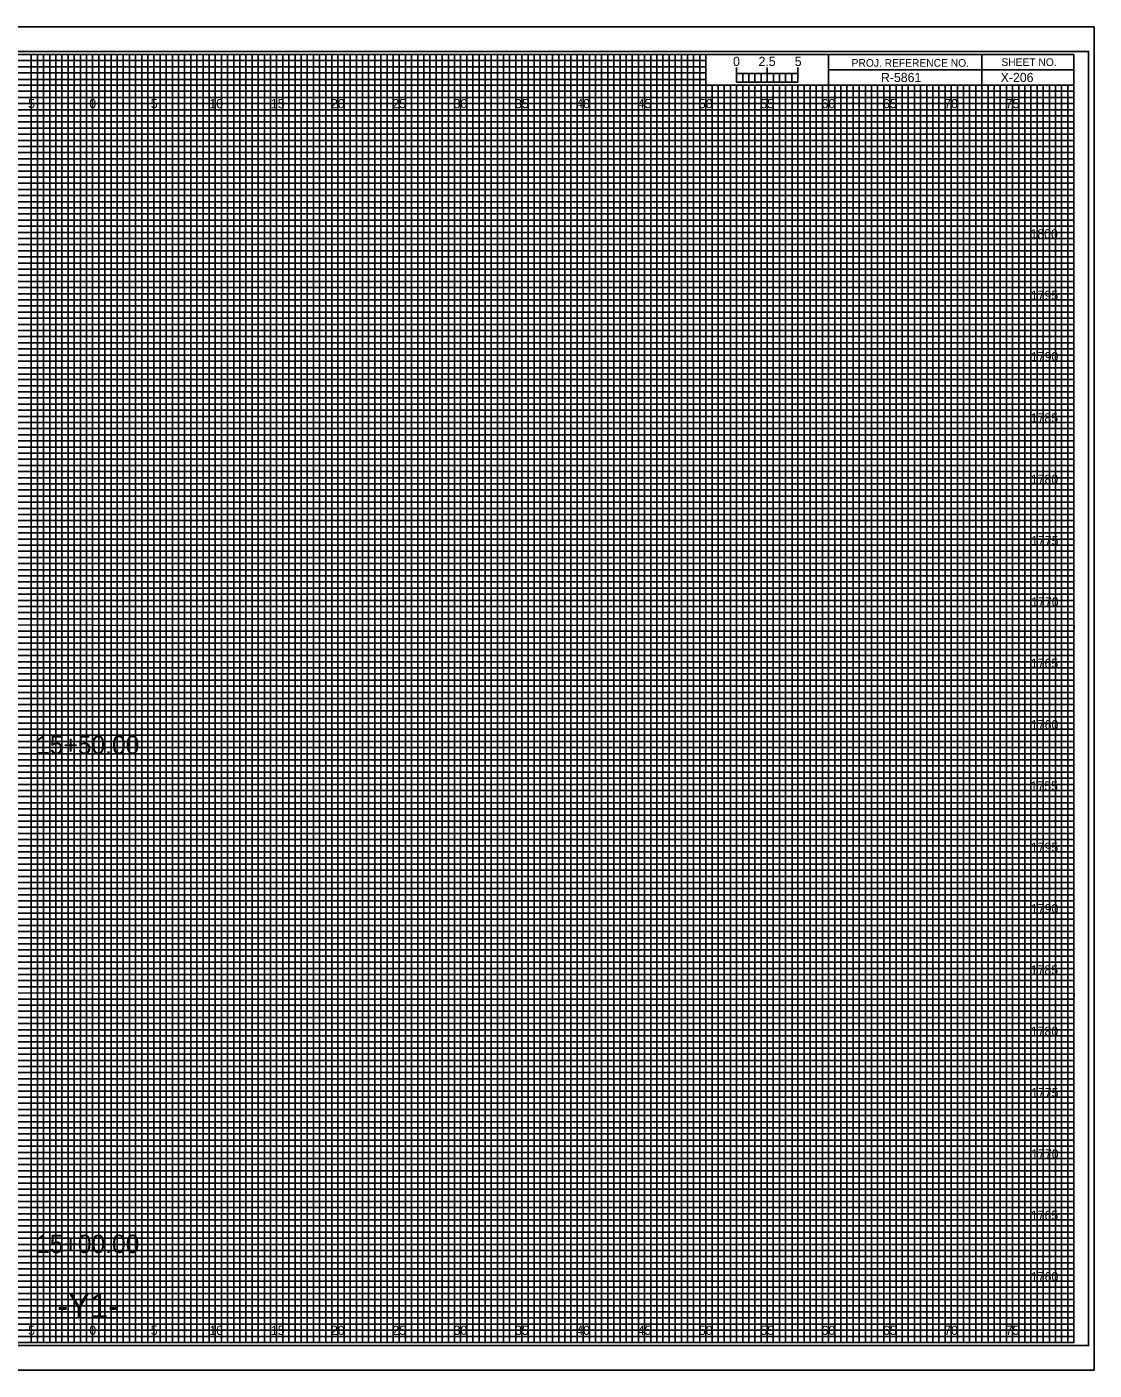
# Model space of a CAD drawing. Extents: x -7 to 162, y -2 to 767.
# Drawn here: x 74.6 to 161.7, y 547.8 to 657.2 of the extents above; entities that cross this region are included whole.
import ezdxf

# ---------------------------------------------------------------- set-up
doc = ezdxf.new("R2010")
doc.units = 0
for name, color, linetype in [('Prop Grid Mask', 7, 'Continuous'), ('Prop XS Alignment Label', 7, 'Continuous'), ('Prop XS Bar Scale Labels', 7, 'Continuous'), ('Prop XS Elevation Labels', 7, 'Continuous'), ('Prop XS Project Number', 7, 'Continuous'), ('Prop XS Sheet Number', 7, 'Continuous'), ('Prop XS Station Labels', 7, 'Continuous'), ('Sheet Cross Section CELL', 7, 'Continuous'), ('Sheet Cross Section Grid Major CELL', 7, 'Continuous'), ('Sheet Cross Section Grid Middle CELL', 7, 'Continuous'), ('Sheet Cross Section Grid Minor 1 CELL', 7, 'Continuous'), ('Sheet Cross Section Grid Minor 2 CELL', 7, 'Continuous'), ('Sheet Cross Section Scale CELL', 7, 'Continuous'), ('Sheet Cutting Line CELL', 7, 'Continuous'), ('Sheet DOT Grid CELL', 7, 'Continuous'), ('Sheet Plot Border Inside CELL', 7, 'Continuous'), ('Sheet Plot Border Outside CELL', 7, 'Continuous')]:
    doc.layers.add(name, color=color, linetype=linetype)

msp = doc.modelspace()

# ---------------------------------------------------------------- linework, layer by layer
at = {"layer": 'Sheet Cross Section CELL'}
for p, q in [((152.5, 655), (152.5, 652.5)), ((152.5, 652.5), (152.5, 655)), ((160, 653.75), (140, 653.75)), ((140, 653.75), (140, 652.5)), ((140, 652.5), (160, 652.5))]:
    msp.add_line(p, q, dxfattribs=at)
for points in [[(160, 655), (0, 655), (0, 550), (160, 550)], [(140, 655), (130, 655), (130, 652.51), (140, 652.51)], [(160, 655), (140, 655), (140, 652.5), (160, 652.5)]]:
    msp.add_lwpolyline(points, close=True, dxfattribs=at)
at = {"layer": 'Sheet Cross Section Grid Major CELL'}
for p, q in [((75, 655), (70, 655)), ((75, 550), (75, 655)), ((85, 655), (80, 655)), ((80, 655), (80, 550)), ((85, 550), (85, 655)), ((95, 655), (90, 655)), ((90, 655), (90, 550)), ((95, 550), (95, 655)), ((105, 655), (100, 655)), ((100, 655), (100, 550)), ((105, 550), (105, 655)), ((115, 655), (110, 655)), ((110, 655), (110, 550)), ((115, 550), (115, 655)), ((125, 655), (120, 655)), ((120, 655), (120, 550)), ((125, 550), (125, 655)), ((130, 655), (130, 550)), ((135, 550), (135, 652.5)), ((145, 652.5), (140, 652.5)), ((140, 652.5), (140, 550)), ((145, 550), (145, 652.5)), ((155, 652.5), (150, 652.5)), ((150, 652.5), (150, 550)), ((155, 550), (155, 652.5)), ((80, 550), (75, 550)), ((90, 550), (85, 550)), ((100, 550), (95, 550)), ((110, 550), (105, 550)), ((120, 550), (115, 550)), ((130, 550), (125, 550)), ((140, 550), (135, 550)), ((150, 550), (145, 550)), ((160, 550), (155, 550)), ((160, 550), (160, 550))]:
    msp.add_line(p, q, dxfattribs=at)
for points in [[(0, 650), (160, 650), (160, 645), (0, 645)], [(0, 640), (160, 640), (160, 635), (0, 635)], [(0, 630), (160, 630), (160, 625), (0, 625)], [(0, 620), (160, 620), (160, 615), (0, 615)], [(0, 610), (160, 610), (160, 605), (0, 605)], [(0, 600), (160, 600), (160, 595), (0, 595)], [(0, 590), (160, 590), (160, 585), (0, 585)], [(0, 580), (160, 580), (160, 575), (0, 575)], [(0, 570), (160, 570), (160, 565), (0, 565)], [(0, 560), (160, 560), (160, 555), (0, 555)]]:
    msp.add_lwpolyline(points, dxfattribs=at)
at = {"layer": 'Sheet Cross Section Grid Middle CELL'}
for points in [[(72.5, 550), (77.5, 550), (77.5, 655), (82.5, 655), (82.5, 550), (87.5, 550), (87.5, 655), (92.5, 655), (92.5, 550), (97.5, 550), (97.5, 655), (102.5, 655), (102.5, 550), (107.5, 550), (107.5, 655), (112.5, 655), (112.5, 550), (117.5, 550), (117.5, 655), (122.5, 655), (122.5, 550), (127.5, 550), (127.5, 655), (129.97, 655), (130, 655), (130, 652.5), (132.5, 652.5), (132.5, 550), (137.5, 550), (137.5, 652.5), (142.5, 652.5), (142.5, 550), (147.5, 550), (147.5, 652.5), (152.5, 652.5), (152.5, 550), (157.5, 550), (157.5, 652.5)], [(0, 652.5), (137.5, 652.5)], [(0, 642.5), (160, 642.5), (160, 647.5), (0, 647.5)], [(0, 632.5), (160, 632.5), (160, 637.5), (0, 637.5)], [(0, 622.5), (160, 622.5), (160, 627.5), (0, 627.5)], [(0, 612.5), (160, 612.5), (160, 617.5), (0, 617.5)], [(0, 602.5), (160, 602.5), (160, 607.5), (0, 607.5)], [(0, 592.5), (160, 592.5), (160, 597.5), (0, 597.5)], [(0, 582.5), (160, 582.5), (160, 587.5), (0, 587.5)], [(0, 572.5), (160, 572.5), (160, 577.5), (0, 577.5)], [(0, 562.5), (160, 562.5), (160, 567.5), (0, 567.5)], [(0, 552.5), (160, 552.5), (160, 557.5), (0, 557.5)]]:
    msp.add_lwpolyline(points, dxfattribs=at)
at = {"layer": 'Sheet Cross Section Grid Minor 1 CELL'}
for p, q in [((0, 654.5), (130, 654.5)), ((130, 653.99), (0, 653.99)), ((130, 654.5), (130, 653.99)), ((0, 653.5), (130, 653.5)), ((130, 652.95), (0, 652.95)), ((130, 653.5), (130, 652.95)), ((0, 652), (160, 652))]:
    msp.add_line(p, q, dxfattribs=at)
for points in [[(0, 651.5), (135, 651.5), (160, 651.5), (160, 651), (0, 651)], [(0, 650.5), (160, 650.5), (160, 649.5), (0, 649.5)], [(0, 649), (160, 649), (160, 648.5), (0, 648.49)], [(0, 648), (160, 648), (160, 647), (0, 647)], [(0, 646.5), (160, 646.5), (160, 646), (0, 646)], [(0, 645.5), (160, 645.5), (160, 644.5), (0, 644.5)], [(0, 644), (160, 644), (160, 643.5), (0, 643.5)], [(0, 643), (160, 643), (160, 642), (0, 642)], [(0, 641.5), (160, 641.5), (160, 641), (0, 641)], [(0, 640.5), (160, 640.5), (160, 639.5), (0, 639.5)], [(0, 639), (160, 639), (160, 638.5), (0, 638.5)], [(0, 638), (160, 638), (160, 636.98), (160, 636.5), (160, 636), (0, 636)], [(0, 637), (160, 637), (160, 636.5), (0, 636.5)], [(0, 635.5), (160, 635.5), (160, 634.5), (0, 634.51)], [(0, 634.51), (160, 634.5), (160, 634), (0, 634)], [(0, 633.5), (160, 633.5), (160, 633), (0, 633)], [(0, 632), (160, 632), (160, 631.5), (0, 631.5)], [(0, 631), (160, 631), (160, 630.5), (0, 630.5)], [(-0.04, 629.45), (160, 629.45), (160, 628.94), (-0.04, 628.94)], [(0, 628.5), (160, 628.5), (160, 628), (0, 628)], [(0, 627), (160, 627), (160, 626.5), (0, 626.5)], [(0, 626), (160, 626), (160, 625.5), (0, 625.5)], [(0, 624.5), (160, 624.5), (160, 624), (0, 624)], [(0, 623.5), (160, 623.5), (160, 623), (0, 623)], [(0, 622), (160, 622), (160, 621.5), (0, 621.5)], [(0, 621), (160, 621), (160, 620.5), (0, 620.5)], [(0, 619.5), (160, 619.5), (160, 618.99), (0, 619)], [(0, 618.5), (160, 618.5), (160, 618), (0, 618)], [(0, 617), (160, 617), (160, 616.5), (0, 616.5)], [(0, 616), (160, 616), (160, 615.5), (0, 615.5)], [(0, 614.5), (160, 614.5), (160, 614), (0, 614)], [(0, 613.5), (160, 613.5), (160, 613), (0, 613)], [(0, 612), (160, 612), (160, 611.5), (0, 611.5)], [(0, 611), (160, 611), (160, 610.5), (0, 610.5)], [(0, 609.5), (160, 609.5), (160, 609), (0, 609)], [(0, 608.5), (160.03, 608.46), (160, 608), (0, 608)], [(0, 607), (160, 607), (160, 606.5), (0, 606.5)], [(0, 606), (160, 606), (160, 605.5), (0, 605.5)], [(0, 604.5), (160, 604.5), (160, 604), (0, 604)], [(0, 603.5), (160, 603.5), (160, 603), (0, 603)], [(0, 602), (160, 602), (160, 601.5), (0, 601.5)], [(0, 601), (160, 601), (160, 600.5), (0, 600.5)], [(0, 599.5), (160, 599.5), (160, 599), (0, 599)], [(0, 598.5), (160, 598.5), (160, 598), (0, 598)], [(0, 597), (160, 597), (160, 596.5), (0, 596.5)], [(0, 596), (160, 596), (160, 595.5), (0, 595.5)], [(0, 594.5), (160, 594.5), (160, 594), (0, 594)], [(0, 593.5), (160, 593.5), (160, 593), (0, 593)], [(0, 592), (160, 592), (160, 591.5), (0, 591.5)], [(0, 591), (160, 591), (160, 590.5), (0, 590.5)], [(0, 589.5), (160, 589.5), (160, 588.99), (0, 589)], [(0, 588.5), (160, 588.5), (160, 588), (0, 588)], [(0, 587), (160, 587), (160, 586.5), (0, 586.5)], [(0, 586), (160, 586), (160, 585.5), (0, 585.5)], [(0, 584.5), (160, 584.5), (160, 584), (0, 584)], [(0, 583.5), (160, 583.5), (160, 583), (0, 583)], [(0, 582), (160, 582), (160, 581.5), (0, 581.5)], [(0, 581), (160, 581), (160, 580.5), (0, 580.5)], [(0, 579.5), (160, 579.5), (160, 579), (0, 579)], [(0, 578.5), (160.03, 578.46), (160, 578), (0, 578)], [(0, 577), (160, 577), (160, 576.5), (0, 576.5)], [(0, 576), (160, 576), (160, 575.5), (0, 575.5)], [(0, 574.5), (160, 574.5), (160, 574), (0, 574)], [(0, 573.5), (160, 573.5), (160, 573), (0, 573)], [(0, 572), (160, 572), (160, 571.5), (0, 571.5)], [(0, 571), (160, 571), (160, 570.5), (0, 570.5)], [(0, 569.5), (160, 569.5), (160, 569), (0, 569)], [(0, 568.5), (160, 568.5), (160, 568), (0, 568)], [(0, 567), (160, 567), (160, 566.5), (0, 566.5)], [(0, 566), (160, 566), (160, 565.5), (0, 565.5)], [(0, 564.5), (160, 564.5), (160, 564), (0, 564)], [(0, 563.5), (160, 563.5), (160, 563), (0, 563)], [(0, 562), (160, 562), (160, 561.5), (0, 561.5)], [(0, 561), (160, 561), (160, 560.5), (0, 560.5)], [(0, 559.5), (160, 559.5), (160, 559), (0, 559)], [(0, 558.5), (160, 558.5), (160, 558), (0, 558)], [(0, 557), (160, 557), (160, 556.5), (0, 556.5)], [(0, 556), (160, 556), (160, 555.5), (0, 555.5)], [(0, 554.5), (160, 554.5), (160, 554), (0, 554)], [(0, 553.5), (160, 553.5), (160, 553), (0, 553)], [(0, 552), (160, 552), (160, 551.5), (0, 551.5)], [(0, 551), (160, 551), (160, 550.5), (0, 550.5)]]:
    msp.add_lwpolyline(points, dxfattribs=at)
at = {"layer": 'Sheet Cross Section Grid Minor 2 CELL'}
for p, q in [((133.5, 652.5), (133, 652.5)), ((133, 652.5), (133, 550)), ((133.5, 550), (133.5, 652.5)), ((134.5, 652.5), (134, 652.5)), ((134, 652.5), (134, 550)), ((134.5, 550), (134.5, 652.5)), ((133, 550), (132.5, 550)), ((134, 550), (133.5, 550))]:
    msp.add_line(p, q, dxfattribs=at)
for points in [[(75, 550), (75.5, 550), (75.5, 655), (76, 655), (76, 550)], [(76, 550), (76.5, 550), (76.5, 655), (77, 655), (77, 550)], [(77.5, 550), (78, 550), (78, 655), (78.5, 655), (78.5, 550)], [(78.5, 550), (79, 550), (79, 655), (79.5, 655), (79.5, 550)], [(80, 550), (80.5, 550), (80.5, 655), (81, 655), (81, 550)], [(81, 550), (81.5, 550), (81.5, 655), (82, 655), (82, 550)], [(82.5, 550), (83, 550), (83, 655), (83.5, 655), (83.5, 550)], [(83.5, 550), (84, 550), (84, 655), (84.5, 655), (84.5, 550)], [(85, 550), (85.5, 550), (85.5, 655), (86, 655), (86, 550)], [(86, 550), (86.5, 550), (86.5, 655), (87, 655), (87, 550)], [(87.5, 550), (88, 550), (88, 655), (88.5, 655), (88.5, 550)], [(88.5, 550), (89, 550), (89, 655), (89.5, 655), (89.5, 550)], [(90, 550), (90.5, 550), (90.5, 655), (91, 655), (91, 550)], [(91, 550), (91.5, 550), (91.5, 655), (92, 655), (92, 550)], [(92.5, 550), (93, 550), (93, 655), (93.5, 655), (93.5, 550)], [(93.5, 550), (94, 550), (94, 655), (94.5, 655), (94.5, 550)], [(95, 550), (95.5, 550), (95.5, 655), (96, 655), (96, 550)], [(96, 550), (96.5, 550), (96.5, 655), (97, 655), (97, 550)], [(97.5, 550), (98, 550), (98, 655), (98.5, 655), (98.5, 550)], [(98.5, 550), (99, 550), (99, 655), (99.5, 655), (99.5, 550)], [(100, 550), (100.5, 550), (100.5, 655), (101, 655), (101, 550)], [(101, 550), (101.5, 550), (101.5, 655), (102, 655), (102, 550)], [(102.5, 550), (103, 550), (103, 655), (103.5, 655), (103.5, 550)], [(103.5, 550), (104, 550), (104, 655), (104.5, 655), (104.5, 550)], [(105, 550), (105.5, 550), (105.5, 655), (106, 655), (106, 550)], [(106, 550), (106.5, 550), (106.5, 655), (107, 655), (107, 550)], [(107.5, 550), (108, 550), (108, 655), (108.5, 655), (108.5, 550)], [(108.5, 550), (109, 550), (109, 655), (109.5, 655), (109.5, 550)], [(110, 550), (110.5, 550), (110.5, 655), (111, 655), (111, 550)], [(111, 550), (111.5, 550), (111.5, 655), (112, 655), (112, 550)], [(112.5, 550), (113, 550), (113, 655), (113.5, 655), (113.5, 550)], [(113.5, 550), (114, 550), (114, 655), (114.5, 655), (114.5, 550)], [(115, 550), (115.5, 550), (115.5, 655), (116, 655), (116, 550)], [(116, 550), (116.5, 550), (116.5, 655), (117, 655), (117, 550)], [(117.5, 550), (118, 550), (118, 655), (118.5, 655), (118.5, 550)], [(118.5, 550), (119, 550), (119, 655), (119.5, 655), (119.5, 550)], [(120, 550), (120.5, 550), (120.5, 655), (121, 655), (121, 550)], [(121, 550), (121.5, 550), (121.5, 655), (122, 655), (122, 550)], [(122.5, 550), (123, 550), (123, 655), (123.5, 655), (123.5, 550)], [(123.5, 550), (124, 550), (124, 655), (124.5, 655), (124.5, 550)], [(125, 550), (125.5, 550), (125.5, 655), (126, 655), (126, 550)], [(126, 550), (126.5, 550), (126.5, 655), (127, 655), (127, 550)], [(127.5, 550), (128, 550), (128, 655), (128.5, 655), (128.5, 550)], [(128.5, 550), (129, 550), (129, 655), (129.5, 655), (129.5, 550)], [(130, 550), (130.5, 550), (130.5, 652.5), (131.01, 652.5), (131.01, 550)], [(131, 550), (131.5, 550), (131.5, 652.5), (132, 652.5), (132, 550)], [(135, 550), (135.49, 550), (135.49, 652.5), (136, 652.5), (136, 550)], [(136, 550), (136.5, 550), (136.5, 652.5), (137.03, 652.5), (137.03, 550)], [(137.5, 550), (138, 550), (138, 652.5), (138.5, 652.5), (138.5, 550)], [(138.5, 550), (139, 550), (139, 652.5), (139.5, 652.5), (139.5, 550)], [(140, 550), (140.5, 550), (140.5, 652.5), (141, 652.5), (141, 550)], [(141, 550), (141.5, 550), (141.5, 652.5), (142, 652.5), (142, 550)], [(142.5, 550), (143, 550), (143, 652.5), (143.5, 652.5), (143.5, 550)], [(143.5, 550), (144, 550), (144, 652.5), (144.5, 652.5), (144.5, 550)], [(145, 550), (145.5, 550), (145.5, 652.5), (146, 652.5), (146, 550)], [(146, 550), (146.5, 550), (146.5, 652.5), (147, 652.5), (147, 550)], [(147.5, 550), (148, 550), (148, 652.5), (148.5, 652.5), (148.5, 550)], [(148.5, 550), (149, 550), (149, 652.5), (149.5, 652.5), (149.5, 550)], [(150, 550), (150.5, 550), (150.5, 652.5), (151, 652.5), (151, 550)], [(151, 550), (151.5, 550), (151.5, 652.5), (152, 652.5), (152, 550)], [(152.5, 550), (153, 550), (153, 652.5), (153.5, 652.5), (153.5, 550)], [(153.5, 550), (154, 550), (154, 652.5), (154.5, 652.5), (154.5, 550)], [(155, 550), (155.5, 550), (155.5, 652.5), (156, 652.5), (156, 550)], [(156, 550), (156.5, 550), (156.5, 652.5), (157, 652.5), (157, 550)], [(157.5, 550), (158, 550), (158, 652.5), (158.5, 652.5), (158.5, 550)], [(158.5, 550), (159, 550), (159, 652.5), (159.5, 652.5), (159.5, 550)]]:
    msp.add_lwpolyline(points, dxfattribs=at)
at = {"layer": 'Sheet Cross Section Scale CELL'}
for p, q in [((132.5, 652.75), (132.5, 653.95)), ((132.5, 653.45), (132.5, 653.95)), ((135, 652.75), (135, 653.95)), ((137.5, 652.75), (137.5, 653.95)), ((137.5, 653.45), (137.5, 653.95))]:
    msp.add_line(p, q, dxfattribs=at)
for points in [[(137.5, 653.45), (132.5, 653.45), (132.5, 652.75), (137.5, 652.75)], [(132.5, 653.45), (133, 653.45), (133, 652.75), (132.5, 652.75)], [(133.5, 653.45), (134, 653.45), (134, 652.75), (133.5, 652.75)], [(134.5, 653.45), (135, 653.45), (135, 652.75), (134.5, 652.75)], [(135.5, 653.45), (136, 653.45), (136, 652.75), (135.5, 652.75)], [(136.5, 653.45), (137, 653.45), (137, 652.75), (136.5, 652.75)]]:
    msp.add_lwpolyline(points, close=True, dxfattribs=at)
at = {"layer": 'Sheet Cutting Line CELL'}
for p, q in [((161.65, 657.25), (-6.7, 657.25)), ((-6.7, 547.75), (161.65, 547.75))]:
    msp.add_line(p, q, dxfattribs=at)
at = {"layer": 'Sheet DOT Grid CELL'}
for p, q in [((75, 550), (75, 655)), ((80, 550), (80, 655)), ((85, 550), (85, 655)), ((90, 550), (90, 655)), ((95, 550), (95, 655)), ((100, 550), (100, 655)), ((105, 550), (105, 655)), ((110, 550), (110, 655)), ((115, 550), (115, 655)), ((120, 550), (120, 655)), ((125, 550), (125, 655)), ((130, 550), (130, 652.34)), ((135, 550), (135, 652.34)), ((140, 550), (140, 652.34)), ((145, 550), (145, 652.34)), ((150, 550), (150, 652.34)), ((155, 550), (155, 652.34)), ((0, 650), (160, 650)), ((0, 645), (160, 645)), ((0, 640), (160, 640)), ((0, 635), (160, 635)), ((0, 630), (160, 630)), ((0, 625), (160, 625)), ((0, 620), (160, 620)), ((0, 615), (160, 615)), ((0, 610), (160, 610)), ((0, 605), (160, 605)), ((0, 600), (160, 600)), ((0, 595), (160, 595)), ((0, 590), (160, 590)), ((0, 585), (160, 585)), ((0, 580), (160, 580)), ((0, 575), (160, 575)), ((0, 570), (160, 570)), ((0, 565), (160, 565)), ((0, 560), (160, 560)), ((0, 555), (160, 555))]:
    msp.add_line(p, q, dxfattribs=at)
at = {"layer": 'Sheet Plot Border Inside CELL'}
msp.add_lwpolyline([(-5.4, 549.75), (161.2, 549.75), (161.2, 655.25), (-5.4, 655.25)], close=True, dxfattribs=at)
at = {"layer": 'Sheet Plot Border Outside CELL'}
msp.add_lwpolyline([(-6.7, 547.75), (161.65, 547.75), (161.65, 657.25), (-6.7, 657.25)], close=True, dxfattribs=at)

# ---------------------------------------------------------------- texts
at = {"layer": 'Prop Grid Mask'}
for s, p in [('5', (74.74, 650.62)), ('0', (79.73, 650.62)), ('0', (79.73, 650.62)), ('5', (84.74, 650.62)), ('10', (89.52, 650.62)), ('15', (94.53, 650.62)), ('20', (99.43, 650.62)), ('25', (104.44, 650.62)), ('30', (109.43, 650.62)), ('35', (114.44, 650.62)), ('40', (119.43, 650.62)), ('45', (124.44, 650.62)), ('50', (129.43, 650.62)), ('55', (134.44, 650.62)), ('60', (139.43, 650.62)), ('65', (144.44, 650.62)), ('70', (149.43, 650.62)), ('75', (154.44, 650.62)), ('5', (74.74, 550.62)), ('0', (79.73, 550.62)), ('0', (79.73, 550.62)), ('5', (84.74, 550.62)), ('10', (89.52, 550.62)), ('15', (94.53, 550.62)), ('20', (99.43, 550.62)), ('25', (104.44, 550.62)), ('30', (109.43, 550.62)), ('35', (114.44, 550.62)), ('40', (119.43, 550.62)), ('45', (124.44, 550.62)), ('50', (129.43, 550.62)), ('55', (134.44, 550.62)), ('60', (139.43, 550.62)), ('65', (144.44, 550.62)), ('70', (149.43, 550.62)), ('75', (154.44, 550.62))]:
    msp.add_text(s, height=0.75, dxfattribs=at).set_placement(p)
at = {"layer": 'Prop XS Alignment Label'}
msp.add_text('-Y1-', height=2, dxfattribs=at).set_placement((77.11, 552))
at = {"layer": 'Prop XS Bar Scale Labels'}
for s, p in [('2.5', (134.29, 654.06)), ('5', (137.24, 654.06))]:
    msp.add_text(s, height=0.75, dxfattribs=at).set_placement(p)
at = {"layer": 'Prop XS Elevation Labels'}
for s, p in [('1800', (156.46, 640)), ('1795', (156.49, 635)), ('1790', (156.5, 630)), ('1785', (156.48, 625)), ('1780', (156.49, 620)), ('1775', (156.51, 615)), ('1770', (156.52, 610)), ('1765', (156.49, 605)), ('1760', (156.5, 600)), ('1755', (156.47, 595)), ('1795', (156.49, 590)), ('1790', (156.5, 585)), ('1785', (156.48, 580)), ('1780', (156.49, 575)), ('1775', (156.51, 570)), ('1770', (156.52, 565)), ('1765', (156.49, 560)), ('1760', (156.5, 555))]:
    msp.add_text(s, height=0.75, dxfattribs=at).set_placement(p)
at = {"layer": 'Prop XS Project Number'}
msp.add_text('R-5861', height=0.75, dxfattribs=at).set_placement((144.27, 652.75))
at = {"layer": 'Prop XS Sheet Number'}
msp.add_text('X-206', height=0.75, dxfattribs=at).set_placement((154.03, 652.75))
at = {"layer": 'Prop XS Station Labels'}
for s, p in [('15+50.00', (75.39, 597.97)), ('15+00.00', (75.39, 557.29))]:
    msp.add_text(s, height=1.5, dxfattribs=at).set_placement(p)
at = {"layer": 'Sheet Cross Section CELL'}
for s, p in [('PROJ. REFERENCE NO.', (141.88, 654)), ('SHEET NO.', (154.09, 654.06))]:
    msp.add_text(s, height=0.625, dxfattribs=at).set_placement(p)
at = {"layer": 'Sheet Cross Section Scale CELL'}
msp.add_text('0', height=0.75, dxfattribs=at).set_placement((132.21, 654.06))

doc.saveas('drawing.dxf')
